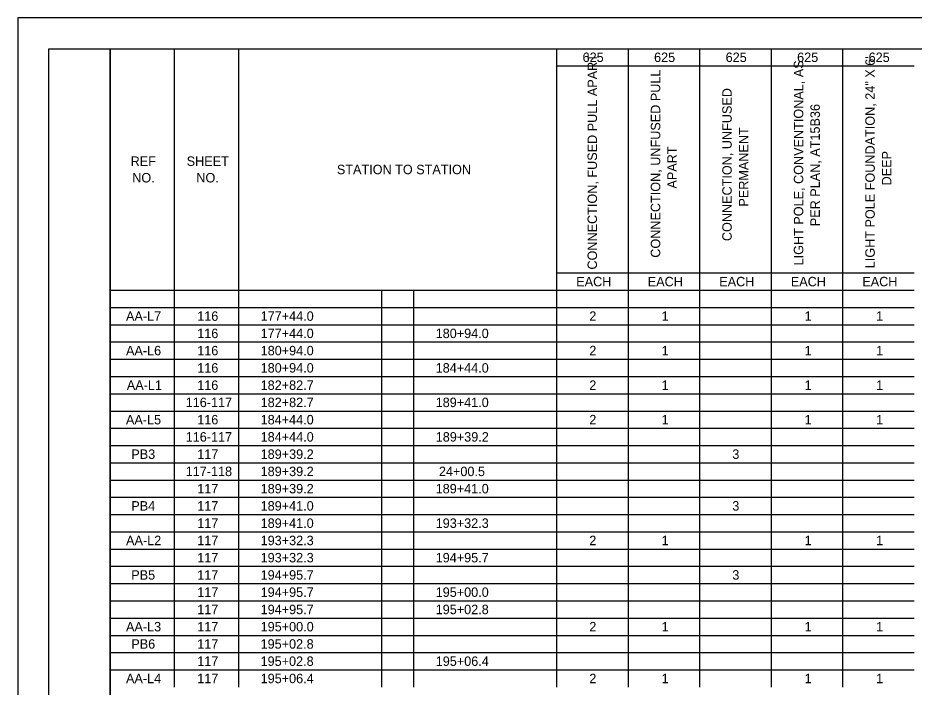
# Model space of a CAD drawing. Extents: x 0 to 34, y 0 to 22.
# Drawn here: x 0 to 14.57, y 11.12 to 22 of the extents above; entities that cross this region are included whole.
import ezdxf

# ---------------------------------------------------------------- set-up
doc = ezdxf.new("R2010")
doc.units = 0
for name, color, linetype in [('SH_Border', 7, 'Continuous'), ('SH_Cut_Line', 7, 'Continuous'), ('SH_Text', 7, 'Continuous')]:
    doc.layers.add(name, color=color, linetype=linetype)

msp = doc.modelspace()

# ---------------------------------------------------------------- linework, layer by layer
at = {"layer": 'SH_Border'}
for points in [[(0.5, 21.5), (1.5, 21.5), (1.5, 0.5), (0.5, 0.5)], [(1.5, 21.5), (33.5, 21.5), (33.5, 0.5), (1.5, 0.5)]]:
    msp.add_lwpolyline(points, close=True, dxfattribs=at)
at = {"layer": 'SH_Cut_Line'}
msp.add_lwpolyline([(0, 0), (34, 0), (34, 22), (0, 22)], close=True, dxfattribs=at)
at = {"layer": 'SH_Text'}
for p, q in [((1.5, 21.5), (5.909, 21.5)), ((1.5, 21.5), (1.5, 21.219)), ((2.542, 21.5), (2.542, 21.219)), ((3.584, 21.5), (3.584, 21.219)), ((5.909, 21.5), (6.43, 21.5)), ((6.43, 21.5), (7.953, 21.5)), ((7.953, 21.5), (11.079, 21.5)), ((8.754, 21.5), (8.754, 21.219)), ((9.917, 21.5), (9.917, 21.219)), ((11.079, 21.5), (12.241, 21.5)), ((11.079, 21.5), (11.079, 21.219)), ((12.241, 21.5), (14.566, 21.5)), ((12.241, 21.5), (12.241, 21.219)), ((13.403, 21.5), (13.403, 21.219)), ((1.5, 21.219), (1.5, 20.939)), ((2.542, 21.219), (2.542, 20.939)), ((3.584, 21.219), (3.584, 20.939)), ((8.754, 21.219), (11.079, 21.219)), ((8.754, 21.219), (8.754, 20.939)), ((9.917, 21.219), (9.917, 20.939)), ((11.079, 21.219), (12.241, 21.219)), ((11.079, 21.219), (11.079, 20.939)), ((12.241, 21.219), (14.566, 21.219)), ((12.241, 21.219), (12.241, 20.939)), ((13.403, 21.219), (13.403, 20.939)), ((1.5, 20.939), (1.5, 20.658)), ((2.542, 20.939), (2.542, 20.658)), ((3.584, 20.939), (3.584, 20.658)), ((8.754, 20.939), (8.754, 20.658)), ((9.917, 20.939), (9.917, 20.658)), ((11.079, 20.939), (11.079, 20.658)), ((12.241, 20.939), (12.241, 20.658)), ((13.403, 20.939), (13.403, 20.658)), ((1.5, 20.658), (1.5, 20.378)), ((2.542, 20.658), (2.542, 20.378)), ((3.584, 20.658), (3.584, 20.378)), ((8.754, 20.658), (8.754, 20.378)), ((9.917, 20.658), (9.917, 20.378)), ((11.079, 20.658), (11.079, 20.378)), ((12.241, 20.658), (12.241, 20.378)), ((13.403, 20.658), (13.403, 20.378)), ((1.5, 20.378), (1.5, 20.097)), ((2.542, 20.378), (2.542, 20.097)), ((3.584, 20.378), (3.584, 20.097)), ((8.754, 20.378), (8.754, 20.097)), ((9.917, 20.378), (9.917, 20.097)), ((11.079, 20.378), (11.079, 20.097)), ((12.241, 20.378), (12.241, 20.097)), ((13.403, 20.378), (13.403, 20.097)), ((1.5, 20.097), (1.5, 19.817)), ((2.542, 20.097), (2.542, 19.817)), ((3.584, 20.097), (3.584, 19.817)), ((8.754, 20.097), (8.754, 19.817)), ((9.917, 20.097), (9.917, 19.817)), ((11.079, 20.097), (11.079, 19.817)), ((12.241, 20.097), (12.241, 19.817)), ((13.403, 20.097), (13.403, 19.817)), ((1.5, 19.817), (1.5, 19.536)), ((2.542, 19.817), (2.542, 19.536)), ((3.584, 19.817), (3.584, 19.536)), ((8.754, 19.817), (8.754, 19.536)), ((9.917, 19.817), (9.917, 19.536)), ((11.079, 19.817), (11.079, 19.536)), ((12.241, 19.817), (12.241, 19.536)), ((13.403, 19.817), (13.403, 19.536)), ((1.5, 19.536), (1.5, 18.975)), ((2.542, 19.536), (2.542, 18.975)), ((3.584, 19.536), (3.584, 18.975)), ((8.754, 19.536), (8.754, 18.975)), ((9.917, 19.536), (9.917, 18.975)), ((11.079, 19.536), (11.079, 18.975)), ((12.241, 19.536), (12.241, 18.975)), ((13.403, 19.536), (13.403, 18.975)), ((1.5, 18.975), (1.5, 18.133)), ((2.542, 18.975), (2.542, 18.133)), ((3.584, 18.975), (3.584, 18.133)), ((8.754, 18.975), (8.754, 18.133)), ((9.917, 18.975), (9.917, 18.133)), ((11.079, 18.975), (11.079, 18.133)), ((12.241, 18.975), (12.241, 18.133)), ((13.403, 18.975), (13.403, 18.133)), ((1.5, 18.133), (1.5, 17.853)), ((2.542, 18.133), (2.542, 17.853)), ((3.584, 18.133), (3.584, 17.853)), ((8.754, 18.133), (8.754, 17.853)), ((9.917, 18.133), (9.917, 17.853)), ((11.079, 18.133), (11.079, 17.853)), ((12.241, 18.133), (12.241, 17.853)), ((13.403, 18.133), (13.403, 17.853)), ((1.5, 17.853), (1.5, 17.292)), ((2.542, 17.853), (2.542, 17.292)), ((3.584, 17.853), (3.584, 17.292)), ((8.754, 17.853), (11.079, 17.853)), ((8.754, 17.853), (8.754, 17.292)), ((9.917, 17.853), (9.917, 17.292)), ((11.079, 17.853), (12.241, 17.853)), ((11.079, 17.853), (11.079, 17.292)), ((12.241, 17.853), (14.566, 17.853)), ((12.241, 17.853), (12.241, 17.292)), ((13.403, 17.853), (13.403, 17.292)), ((1.5, 17.572), (5.909, 17.572)), ((5.909, 17.572), (6.43, 17.572)), ((5.909, 17.572), (5.909, 17.292)), ((6.43, 17.572), (7.953, 17.572)), ((6.43, 17.572), (6.43, 17.292)), ((7.953, 17.572), (11.079, 17.572)), ((11.079, 17.572), (12.241, 17.572)), ((12.241, 17.572), (14.566, 17.572)), ((1.5, 17.292), (5.909, 17.292)), ((1.5, 17.292), (1.5, 17.011)), ((2.542, 17.292), (2.542, 17.011)), ((3.584, 17.292), (3.584, 17.011)), ((5.909, 17.292), (6.43, 17.292)), ((5.909, 17.292), (5.909, 17.011)), ((6.43, 17.292), (7.953, 17.292)), ((6.43, 17.292), (6.43, 17.011)), ((7.953, 17.292), (11.079, 17.292)), ((8.754, 17.292), (8.754, 17.011)), ((9.917, 17.292), (9.917, 17.011)), ((11.079, 17.292), (12.241, 17.292)), ((11.079, 17.292), (11.079, 17.011)), ((12.241, 17.292), (14.566, 17.292)), ((12.241, 17.292), (12.241, 17.011)), ((13.403, 17.292), (13.403, 17.011)), ((1.5, 17.011), (5.909, 17.011)), ((1.5, 17.011), (1.5, 15.889)), ((2.542, 17.011), (2.542, 15.889)), ((3.584, 17.011), (3.584, 15.889)), ((5.909, 17.011), (6.43, 17.011)), ((5.909, 17.011), (5.909, 15.889)), ((6.43, 17.011), (7.953, 17.011)), ((6.43, 17.011), (6.43, 15.889)), ((7.953, 17.011), (11.079, 17.011)), ((8.754, 17.011), (8.754, 15.889)), ((9.917, 17.011), (9.917, 15.889)), ((11.079, 17.011), (12.241, 17.011)), ((11.079, 17.011), (11.079, 15.889)), ((12.241, 17.011), (14.566, 17.011)), ((12.241, 17.011), (12.241, 15.889)), ((13.403, 17.011), (13.403, 15.889)), ((1.5, 16.731), (5.909, 16.731)), ((5.909, 16.731), (6.43, 16.731)), ((6.43, 16.731), (7.953, 16.731)), ((7.953, 16.731), (11.079, 16.731)), ((11.079, 16.731), (12.241, 16.731)), ((12.241, 16.731), (14.566, 16.731)), ((1.5, 16.45), (5.909, 16.45)), ((5.909, 16.45), (6.43, 16.45)), ((6.43, 16.45), (7.953, 16.45)), ((7.953, 16.45), (11.079, 16.45)), ((11.079, 16.45), (12.241, 16.45)), ((12.241, 16.45), (14.566, 16.45)), ((1.5, 16.17), (5.909, 16.17)), ((5.909, 16.17), (6.43, 16.17)), ((6.43, 16.17), (7.953, 16.17)), ((7.953, 16.17), (11.079, 16.17)), ((11.079, 16.17), (12.241, 16.17)), ((12.241, 16.17), (14.566, 16.17)), ((1.5, 15.889), (5.909, 15.889)), ((1.5, 15.889), (1.5, 15.608)), ((2.542, 15.889), (2.542, 15.608)), ((3.584, 15.889), (3.584, 15.608)), ((5.909, 15.889), (6.43, 15.889)), ((5.909, 15.889), (5.909, 15.608)), ((6.43, 15.889), (7.953, 15.889)), ((6.43, 15.889), (6.43, 15.608)), ((7.953, 15.889), (11.079, 15.889)), ((8.754, 15.889), (8.754, 15.608)), ((9.917, 15.889), (9.917, 15.608)), ((11.079, 15.889), (12.241, 15.889)), ((11.079, 15.889), (11.079, 15.608)), ((12.241, 15.889), (14.566, 15.889)), ((12.241, 15.889), (12.241, 15.608)), ((13.403, 15.889), (13.403, 15.608)), ((1.5, 15.608), (5.909, 15.608)), ((1.5, 15.608), (1.5, 15.047)), ((2.542, 15.608), (2.542, 15.047)), ((3.584, 15.608), (3.584, 15.047)), ((5.909, 15.608), (6.43, 15.608)), ((5.909, 15.608), (5.909, 15.047)), ((6.43, 15.608), (7.953, 15.608)), ((6.43, 15.608), (6.43, 15.047)), ((7.953, 15.608), (11.079, 15.608)), ((8.754, 15.608), (8.754, 15.047)), ((9.917, 15.608), (9.917, 15.047)), ((11.079, 15.608), (12.241, 15.608)), ((11.079, 15.608), (11.079, 15.047)), ((12.241, 15.608), (14.566, 15.608)), ((12.241, 15.608), (12.241, 15.047)), ((13.403, 15.608), (13.403, 15.047)), ((1.5, 15.328), (5.909, 15.328)), ((5.909, 15.328), (6.43, 15.328)), ((6.43, 15.328), (7.953, 15.328)), ((7.953, 15.328), (11.079, 15.328)), ((11.079, 15.328), (12.241, 15.328)), ((12.241, 15.328), (14.566, 15.328)), ((1.5, 15.047), (5.909, 15.047)), ((1.5, 15.047), (1.5, 14.486)), ((2.542, 15.047), (2.542, 14.486)), ((3.584, 15.047), (3.584, 14.486)), ((5.909, 15.047), (6.43, 15.047)), ((5.909, 15.047), (5.909, 14.486)), ((6.43, 15.047), (7.953, 15.047)), ((6.43, 15.047), (6.43, 14.486)), ((7.953, 15.047), (11.079, 15.047)), ((8.754, 15.047), (8.754, 14.486)), ((9.917, 15.047), (9.917, 14.486)), ((11.079, 15.047), (12.241, 15.047)), ((11.079, 15.047), (11.079, 14.486)), ((12.241, 15.047), (14.566, 15.047)), ((12.241, 15.047), (12.241, 14.486)), ((13.403, 15.047), (13.403, 14.486)), ((1.5, 14.767), (5.909, 14.767)), ((5.909, 14.767), (6.43, 14.767)), ((6.43, 14.767), (7.953, 14.767)), ((7.953, 14.767), (11.079, 14.767)), ((11.079, 14.767), (12.241, 14.767)), ((12.241, 14.767), (14.566, 14.767)), ((1.5, 14.486), (5.909, 14.486)), ((1.5, 14.486), (1.5, 14.206)), ((2.542, 14.486), (2.542, 14.206)), ((3.584, 14.486), (3.584, 14.206)), ((5.909, 14.486), (6.43, 14.486)), ((5.909, 14.486), (5.909, 14.206)), ((6.43, 14.486), (7.953, 14.486)), ((6.43, 14.486), (6.43, 14.206)), ((7.953, 14.486), (11.079, 14.486)), ((8.754, 14.486), (8.754, 14.206)), ((9.917, 14.486), (9.917, 14.206)), ((11.079, 14.486), (12.241, 14.486)), ((11.079, 14.486), (11.079, 14.206)), ((12.241, 14.486), (14.566, 14.486)), ((12.241, 14.486), (12.241, 14.206)), ((13.403, 14.486), (13.403, 14.206)), ((1.5, 14.206), (5.909, 14.206)), ((1.5, 14.206), (1.5, 13.645)), ((2.542, 14.206), (2.542, 13.645)), ((3.584, 14.206), (3.584, 13.645)), ((5.909, 14.206), (6.43, 14.206)), ((5.909, 14.206), (5.909, 13.645)), ((6.43, 14.206), (7.953, 14.206)), ((6.43, 14.206), (6.43, 13.645)), ((7.953, 14.206), (11.079, 14.206)), ((8.754, 14.206), (8.754, 13.645)), ((9.917, 14.206), (9.917, 13.645)), ((11.079, 14.206), (12.241, 14.206)), ((11.079, 14.206), (11.079, 13.645)), ((12.241, 14.206), (14.566, 14.206)), ((12.241, 14.206), (12.241, 13.645)), ((13.403, 14.206), (13.403, 13.645)), ((1.5, 13.925), (5.909, 13.925)), ((5.909, 13.925), (6.43, 13.925)), ((6.43, 13.925), (7.953, 13.925)), ((7.953, 13.925), (11.079, 13.925)), ((11.079, 13.925), (12.241, 13.925)), ((12.241, 13.925), (14.566, 13.925)), ((1.5, 13.645), (5.909, 13.645)), ((1.5, 13.645), (1.5, 13.364)), ((2.542, 13.645), (2.542, 13.364)), ((3.584, 13.645), (3.584, 13.364)), ((5.909, 13.645), (6.43, 13.645)), ((5.909, 13.645), (5.909, 13.364)), ((6.43, 13.645), (7.953, 13.645)), ((6.43, 13.645), (6.43, 13.364)), ((7.953, 13.645), (11.079, 13.645)), ((8.754, 13.645), (8.754, 13.364)), ((9.917, 13.645), (9.917, 13.364)), ((11.079, 13.645), (12.241, 13.645)), ((11.079, 13.645), (11.079, 13.364)), ((12.241, 13.645), (14.566, 13.645)), ((12.241, 13.645), (12.241, 13.364)), ((13.403, 13.645), (13.403, 13.364)), ((1.5, 13.364), (5.909, 13.364)), ((1.5, 13.364), (1.5, 12.522)), ((2.542, 13.364), (2.542, 12.522)), ((3.584, 13.364), (3.584, 12.522)), ((5.909, 13.364), (6.43, 13.364)), ((5.909, 13.364), (5.909, 12.522)), ((6.43, 13.364), (7.953, 13.364)), ((6.43, 13.364), (6.43, 12.522)), ((7.953, 13.364), (11.079, 13.364)), ((8.754, 13.364), (8.754, 12.522)), ((9.917, 13.364), (9.917, 12.522)), ((11.079, 13.364), (12.241, 13.364)), ((11.079, 13.364), (11.079, 12.522)), ((12.241, 13.364), (14.566, 13.364)), ((12.241, 13.364), (12.241, 12.522)), ((13.403, 13.364), (13.403, 12.522)), ((1.5, 13.083), (5.909, 13.083)), ((5.909, 13.083), (6.43, 13.083)), ((6.43, 13.083), (7.953, 13.083)), ((7.953, 13.083), (11.079, 13.083)), ((11.079, 13.083), (12.241, 13.083)), ((12.241, 13.083), (14.566, 13.083)), ((1.5, 12.803), (5.909, 12.803)), ((5.909, 12.803), (6.43, 12.803)), ((6.43, 12.803), (7.953, 12.803)), ((7.953, 12.803), (11.079, 12.803)), ((11.079, 12.803), (12.241, 12.803)), ((12.241, 12.803), (14.566, 12.803)), ((1.5, 12.522), (5.909, 12.522)), ((1.5, 12.522), (1.5, 11.961)), ((2.542, 12.522), (2.542, 11.961)), ((3.584, 12.522), (3.584, 11.961)), ((5.909, 12.522), (6.43, 12.522)), ((5.909, 12.522), (5.909, 11.961)), ((6.43, 12.522), (7.953, 12.522)), ((6.43, 12.522), (6.43, 11.961)), ((7.953, 12.522), (11.079, 12.522)), ((8.754, 12.522), (8.754, 11.961)), ((9.917, 12.522), (9.917, 11.961)), ((11.079, 12.522), (12.241, 12.522)), ((11.079, 12.522), (11.079, 11.961)), ((12.241, 12.522), (14.566, 12.522)), ((12.241, 12.522), (12.241, 11.961)), ((13.403, 12.522), (13.403, 11.961)), ((1.5, 12.242), (5.909, 12.242)), ((5.909, 12.242), (6.43, 12.242)), ((6.43, 12.242), (7.953, 12.242)), ((7.953, 12.242), (11.079, 12.242)), ((11.079, 12.242), (12.241, 12.242)), ((12.241, 12.242), (14.566, 12.242)), ((1.5, 11.961), (5.909, 11.961)), ((1.5, 11.961), (1.5, 11.12)), ((2.542, 11.961), (2.542, 11.12)), ((3.584, 11.961), (3.584, 11.12)), ((5.909, 11.961), (6.43, 11.961)), ((5.909, 11.961), (5.909, 11.12)), ((6.43, 11.961), (7.953, 11.961)), ((6.43, 11.961), (6.43, 11.12)), ((7.953, 11.961), (11.079, 11.961)), ((8.754, 11.961), (8.754, 11.12)), ((9.917, 11.961), (9.917, 11.12)), ((11.079, 11.961), (12.241, 11.961)), ((11.079, 11.961), (11.079, 11.12)), ((12.241, 11.961), (14.566, 11.961)), ((12.241, 11.961), (12.241, 11.12)), ((13.403, 11.961), (13.403, 11.12)), ((1.5, 11.681), (5.909, 11.681)), ((5.909, 11.681), (6.43, 11.681)), ((6.43, 11.681), (7.953, 11.681)), ((7.953, 11.681), (11.079, 11.681)), ((11.079, 11.681), (12.241, 11.681)), ((12.241, 11.681), (14.566, 11.681)), ((1.5, 11.4), (5.909, 11.4)), ((5.909, 11.4), (6.43, 11.4)), ((6.43, 11.4), (7.953, 11.4)), ((7.953, 11.4), (11.079, 11.4)), ((11.079, 11.4), (12.241, 11.4)), ((12.241, 11.4), (14.566, 11.4))]:
    msp.add_line(p, q, dxfattribs=at)

# ---------------------------------------------------------------- texts
for s, height, p in [('625', 0.1536, (9.178, 21.283)), ('625', 0.1536, (10.34, 21.283)), ('625', 0.1536, (11.503, 21.283)), ('625', 0.1536, (12.665, 21.283)), ('625', 0.1536, (13.827, 21.283)), ('REF', 0.1536, (1.832, 19.594)), ('SHEET', 0.1536, (2.743, 19.594)), ('STATION TO STATION', 0.15364, (5.184, 19.459)), ('NO.', 0.1536, (1.858, 19.325)), ('NO.', 0.1536, (2.9, 19.325)), ('EACH', 0.1536, (9.075, 17.636)), ('EACH', 0.1536, (10.237, 17.636)), ('EACH', 0.1536, (11.399, 17.636)), ('EACH', 0.1536, (12.562, 17.636)), ('EACH', 0.1536, (13.724, 17.636)), ('AA-L7', 0.1536, (1.757, 17.075)), ('116', 0.1536, (2.914, 17.075)), ('177+44.0', 0.1536, (3.945, 17.075)), ('2', 0.154, (9.287, 17.075)), ('1', 0.154, (10.462, 17.075)), ('1', 0.154, (12.786, 17.075)), ('1', 0.154, (13.949, 17.075)), ('116', 0.1536, (2.914, 16.794)), ('177+44.0', 0.1536, (3.945, 16.794)), ('180+94.0', 0.1536, (6.79, 16.794)), ('AA-L6', 0.1536, (1.757, 16.514)), ('116', 0.1536, (2.914, 16.514)), ('180+94.0', 0.1536, (3.945, 16.514)), ('2', 0.154, (9.287, 16.514)), ('1', 0.154, (10.462, 16.514)), ('1', 0.154, (12.786, 16.514)), ('1', 0.154, (13.949, 16.514)), ('116', 0.1536, (2.914, 16.233)), ('180+94.0', 0.1536, (3.945, 16.233)), ('184+44.0', 0.1536, (6.79, 16.233)), ('AA-L1', 0.1536, (1.77, 15.952)), ('116', 0.1536, (2.914, 15.952)), ('182+82.7', 0.1536, (3.945, 15.952)), ('2', 0.154, (9.287, 15.952)), ('1', 0.154, (10.462, 15.952)), ('1', 0.154, (12.786, 15.952)), ('1', 0.154, (13.949, 15.952)), ('116-117', 0.1536, (2.727, 15.672)), ('182+82.7', 0.1536, (3.945, 15.672)), ('189+41.0', 0.1536, (6.79, 15.672)), ('AA-L5', 0.1536, (1.756, 15.391)), ('116', 0.1536, (2.914, 15.391)), ('184+44.0', 0.1536, (3.945, 15.391)), ('2', 0.154, (9.287, 15.391)), ('1', 0.154, (10.462, 15.391)), ('1', 0.154, (12.786, 15.391)), ('1', 0.154, (13.949, 15.391)), ('116-117', 0.1536, (2.727, 15.111)), ('184+44.0', 0.1536, (3.945, 15.111)), ('189+39.2', 0.1536, (6.791, 15.111)), ('PB3', 0.1536, (1.843, 14.83)), ('117', 0.1536, (2.914, 14.83)), ('189+39.2', 0.1536, (3.945, 14.83)), ('3', 0.154, (11.611, 14.83)), ('117-118', 0.1536, (2.727, 14.55)), ('189+39.2', 0.1536, (3.945, 14.55)), ('24+00.5', 0.1536, (6.843, 14.55)), ('117', 0.1536, (2.914, 14.269)), ('189+39.2', 0.1536, (3.945, 14.269)), ('189+41.0', 0.1536, (6.79, 14.269)), ('PB4', 0.1536, (1.843, 13.989)), ('117', 0.1536, (2.914, 13.989)), ('189+41.0', 0.1536, (3.945, 13.989)), ('3', 0.154, (11.611, 13.989)), ('117', 0.1536, (2.914, 13.708)), ('189+41.0', 0.1536, (3.945, 13.708)), ('193+32.3', 0.1536, (6.79, 13.708)), ('AA-L2', 0.1536, (1.758, 13.427)), ('117', 0.1536, (2.914, 13.427)), ('193+32.3', 0.1536, (3.945, 13.427)), ('2', 0.154, (9.287, 13.427)), ('1', 0.154, (10.462, 13.427)), ('1', 0.154, (12.786, 13.427)), ('1', 0.154, (13.949, 13.427)), ('117', 0.1536, (2.914, 13.147)), ('193+32.3', 0.1536, (3.945, 13.147)), ('194+95.7', 0.1536, (6.79, 13.147)), ('PB5', 0.1536, (1.842, 12.866)), ('117', 0.1536, (2.914, 12.866)), ('194+95.7', 0.1536, (3.945, 12.866)), ('3', 0.154, (11.611, 12.866)), ('117', 0.1536, (2.914, 12.586)), ('194+95.7', 0.1536, (3.945, 12.586)), ('195+00.0', 0.1536, (6.79, 12.586)), ('117', 0.1536, (2.914, 12.305)), ('194+95.7', 0.1536, (3.945, 12.305)), ('195+02.8', 0.1536, (6.79, 12.305)), ('AA-L3', 0.1536, (1.757, 12.025)), ('117', 0.1536, (2.914, 12.025)), ('195+00.0', 0.1536, (3.945, 12.025)), ('2', 0.154, (9.287, 12.025)), ('1', 0.154, (10.462, 12.025)), ('1', 0.154, (12.786, 12.025)), ('1', 0.154, (13.949, 12.025)), ('PB6', 0.1536, (1.843, 11.744)), ('117', 0.1536, (2.914, 11.744)), ('195+02.8', 0.1536, (3.944, 11.744)), ('117', 0.1536, (2.914, 11.464)), ('195+02.8', 0.1536, (3.944, 11.464)), ('195+06.4', 0.1536, (6.791, 11.464)), ('AA-L4', 0.1536, (1.757, 11.183)), ('117', 0.1536, (2.914, 11.183)), ('195+06.4', 0.1536, (3.945, 11.183)), ('2', 0.154, (9.287, 11.183)), ('1', 0.154, (10.462, 11.183)), ('1', 0.154, (12.786, 11.183)), ('1', 0.154, (13.949, 11.183))]:
    msp.add_text(s, height=height, dxfattribs=at).set_placement(p)
for s, height, p in [('CONNECTION, FUSED PULL APART', 0.15364, (9.412, 17.908)), ('LIGHT POLE, CONVENTIONAL, AS ', 0.15364, (12.765, 17.976)), ('LIGHT POLE FOUNDATION, 24" X 6\' ', 0.15364, (13.927, 17.93)), ('CONNECTION, UNFUSED PULL ', 0.15364, (10.44, 18.101)), ('CONNECTION, UNFUSED ', 0.15364, (11.602, 18.371)), ('PER PLAN, AT15B36', 0.15364, (13.034, 18.613)), ('PERMANENT', 0.1536, (11.871, 18.932)), ('APART', 0.1536, (10.709, 19.225)), ('DEEP', 0.1536, (14.196, 19.277))]:
    msp.add_text(s, height=height, rotation=90, dxfattribs=at).set_placement(p)

doc.saveas('drawing.dxf')
